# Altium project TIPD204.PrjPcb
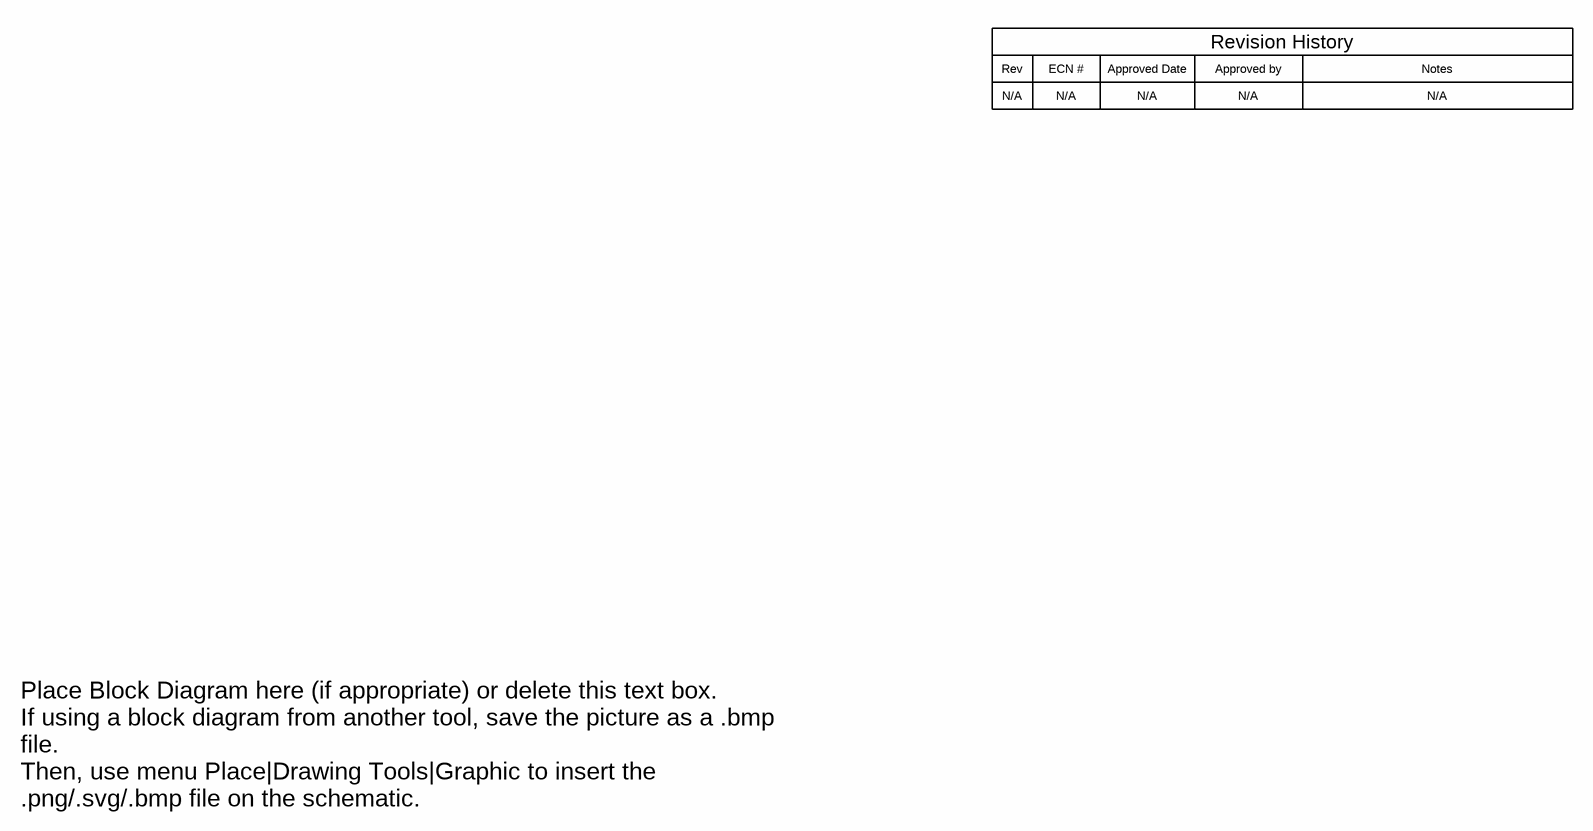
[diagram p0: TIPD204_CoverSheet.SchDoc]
TID: N/A; TechSupport: http://www.ti.com/support; SCH_Rev: A; PRJ_Title: Low-Cost Digitally Programmable Amplifier; PRJ_Number: TIPD204; PRJ_Engineer: CW + JB; PRJ_Customer: Public Release; PCB_Rev: E1; PCB_Layout: JB; CopyrightYear: 2015
3 sheets, 74 parts. Net scope: global (net labels, ports and power ports of the same name join across sheets).
Board file: TIPD204.PcbDoc
Sheets:
  TIPD204_CoverSheet.SchDoc
  TIPD204.SchDoc
  TIPD204_Applications_Hardware.SchDoc

## Sheet TIPD204_CoverSheet.SchDoc
size 431 x 279 mm; Date: Not shown in title block; ApprovedBy: Not shown in title block; CheckedBy: Not shown in title block; Author: Not shown in title block; CompanyName: Not shown in title block; Engineer: Not shown in title block; Organization: Not shown in title block; Address1: Not shown in title block; Address2: Not shown in title block; Address3: Not shown in title block; Address4: Not shown in title block; DocumentNumber: 1; Revision: Use project parameter SCH_Rev; SheetNumber: 1; SheetTotal: 3; PageSetup: Record=PageOptions¦CenterHorizontal=True¦CenterVertical=True¦PrintScale=1.00¦XCorrection=1.00¦YCorrection=1.00¦PrintKind=0¦BorderSize=5000000¦LeftOffset=0¦BottomOffset=0¦Orientation=2¦PaperLength=1000¦PaperWidth=1000¦Scale=100¦PaperSource=15¦PrintQuality=600¦MediaType=1¦DitherType=10¦PaperKind=Letter¦PrintScaleMode=1

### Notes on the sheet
- Rev
- N/A
- ECN #
- Approved Date
- Approved by
- Revision History
- Notes
- Place Block Diagram here (if appropriate) or delete this text box.
  If using a block diagram from another tool, save the picture as a .bmp file.
  Then, use menu Place|Drawing Tools|Graphic to insert the .png/.svg/.bmp file on the schematic.

## Sheet TIPD204.SchDoc: TIPD204
size 431 x 279 mm; Date: Not shown in title block; ApprovedBy: Not shown in title block; CheckedBy: Not shown in title block; Author: Not shown in title block; CompanyName: Not shown in title block; Engineer: CW + JB; Organization: Not shown in title block; Address1: Not shown in title block; Address2: Not shown in title block; Address3: Not shown in title block; Address4: Not shown in title block; DocumentNumber: 1; Revision: Use project parameter SCH_Rev; SheetNumber: 2; SheetTotal: 3; PageSetup: Record=PageOptions¦CenterHorizontal=True¦CenterVertical=True¦PrintScale=1.00¦XCorrection=1.00¦YCorrection=1.00¦PrintKind=0¦BorderSize=5000000¦LeftOffset=0¦BottomOffset=0¦Orientation=2¦PaperLength=1000¦PaperWidth=1000¦Scale=100¦PaperSource=15¦PrintQuality=600¦MediaType=1¦DitherType=10¦PaperKind=Letter¦PrintScaleMode=1
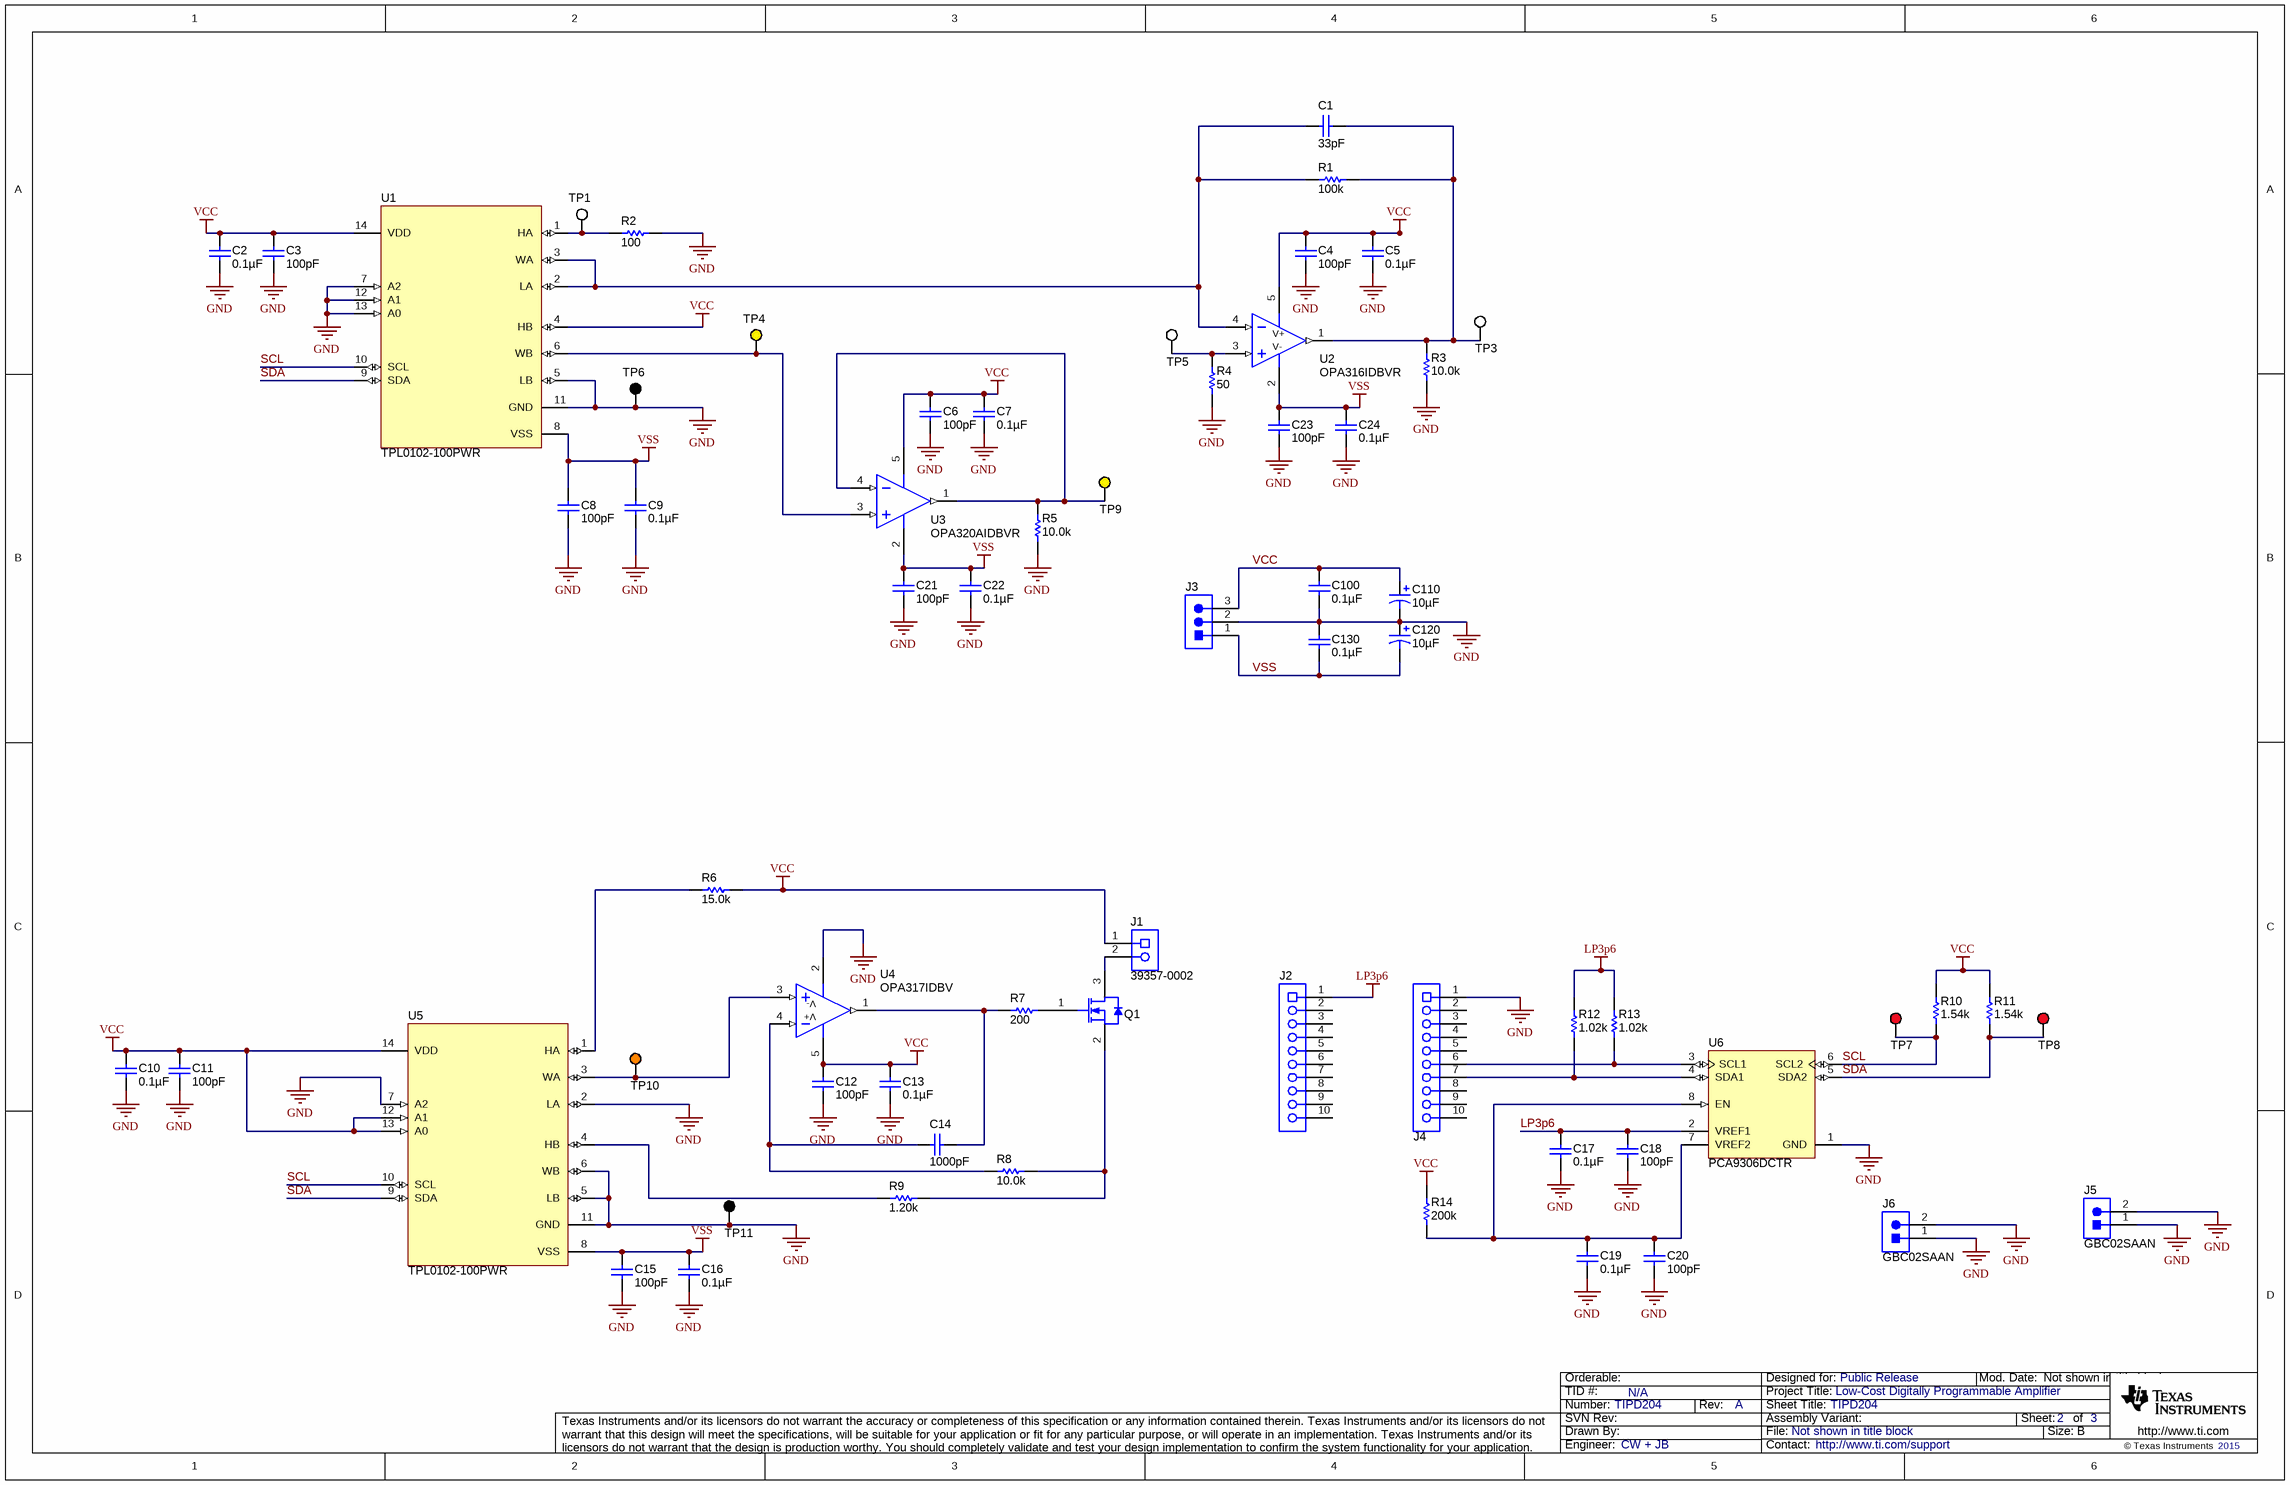
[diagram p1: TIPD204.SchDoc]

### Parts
C1  ValueDisplayed: 33pF  [0603]  (hidden comment: GRM1885C1H330JA01D)
C2  ValueDisplayed: 0.1µF  [0603]  (hidden comment: C0603C104J3RAC)
C3  ValueDisplayed: 100pF  [0603]  (hidden comment: 06033C101KAT2A)
C4  ValueDisplayed: 100pF  [0603]  (hidden comment: 06033C101KAT2A)
C5  ValueDisplayed: 0.1µF  [0603]  (hidden comment: C0603C104J3RAC)
C6  ValueDisplayed: 100pF  [0603]  (hidden comment: 06033C101KAT2A)
C7  ValueDisplayed: 0.1µF  [0603]  (hidden comment: C0603C104J3RAC)
C8  ValueDisplayed: 100pF  [0603]  (hidden comment: 06033C101KAT2A)
C9  ValueDisplayed: 0.1µF  [0603]  (hidden comment: GRM188R71E104KA01D)
C10  ValueDisplayed: 0.1µF  [0603]  (hidden comment: C0603C104J3RAC)
C11  ValueDisplayed: 100pF  [0603]  (hidden comment: 06033C101KAT2A)
C12  ValueDisplayed: 100pF  [0603]  (hidden comment: 06033C101KAT2A)
C13  ValueDisplayed: 0.1µF  [0603]  (hidden comment: C0603C104J3RAC)
C14  ValueDisplayed: 1000pF  [0603]  (hidden comment: 06035A102KAT2A)
C15  ValueDisplayed: 100pF  [0603]  (hidden comment: 06033C101KAT2A)
C16  ValueDisplayed: 0.1µF  [0603]  (hidden comment: C0603C104J3RAC)
C17  ValueDisplayed: 0.1µF  [0603]  (hidden comment: C0603C104J3RAC)
C18  ValueDisplayed: 100pF  [0603]  (hidden comment: 06033C101KAT2A)
C19  ValueDisplayed: 0.1µF  [0603]  (hidden comment: C0603C104J3RAC)
C20  ValueDisplayed: 100pF  [0603]  (hidden comment: 06033C101KAT2A)
C21  ValueDisplayed: 100pF  [0603]  (hidden comment: 06033C101KAT2A)
C22  ValueDisplayed: 0.1µF  [0603]  (hidden comment: C0603C104J3RAC)
C23  ValueDisplayed: 100pF  [0603]  (hidden comment: 06033C101KAT2A)
C24  ValueDisplayed: 0.1µF  [0603]  (hidden comment: C0603C104J3RAC)
C100  ValueDisplayed: 0.1µF  [0603]  (hidden comment: C0603C104J3RAC)
C110  ValueDisplayed: 10µF  [3216-18]  (hidden comment: 293D106X96R3A2TE3)
C120  ValueDisplayed: 10µF  [3216-18]  (hidden comment: 293D106X96R3A2TE3)
C130  ValueDisplayed: 0.1µF  [0603]  (hidden comment: C0603C104J3RAC)
J1  39357-0002  [Molex_39357-0002]
J2  PPTC101LFBN-RC  [CONN_PPTC101LFBN-RC]  (value not drawn)
J3  GBC03SAAN  [Sullins_Gxx03SAAN]  (value not drawn)
J4  PPTC101LFBN-RC  [CONN_PPTC101LFBN-RC]  (value not drawn)
J5  GBC02SAAN  [Sullins_Gxx02SAAN]
J6  GBC02SAAN  [Sullins_Gxx02SAAN]
Q1  SI2304DDS-T1-GE3  [SOT-23]  (value not drawn)
R1  ValueDisplayed: 100k  [0603]  (hidden comment: RC0603FR-07100KL)
R2  ValueDisplayed: 100  [0603]  (hidden comment: RC0603FR-07100RL)
R3  ValueDisplayed: 10.0k  [0603]  (hidden comment: CRCW060310K0FKEA)
R4  ValueDisplayed: 50  [0603]  (hidden comment: CRCW060350R0FKEA)
R5  ValueDisplayed: 10.0k  [0603]  (hidden comment: CRCW060310K0FKEA)
R6  ValueDisplayed: 15.0k  [0603]  (hidden comment: RG1608P-153-B-T5)
R7  ValueDisplayed: 200  [0603]  (hidden comment: RG1608P-201-B-T5)
R8  ValueDisplayed: 10.0k  [0603]  (hidden comment: RG1608P-103-B-T5)
R9  ValueDisplayed: 1.20k  [0603]  (hidden comment: RG1608P-122-B-T5)
R10  ValueDisplayed: 1.54k  [0603]  (hidden comment: CRCW06031K54FKEA)
R11  ValueDisplayed: 1.54k  [0603]  (hidden comment: CRCW06031K54FKEA)
R12  ValueDisplayed: 1.02k  [0603]  (hidden comment: CRCW06031K02FKEA)
R13  ValueDisplayed: 1.02k  [0603]  (hidden comment: CRCW06031K02FKEA)
R14  ValueDisplayed: 200k  [0603]  (hidden comment: CRCW0603200KFKEA)
TP1  5007  [Keystone5007]  (value not drawn)
TP3  5007  [Keystone5007]  (value not drawn)
TP4  5009  [Keystone5009]  (value not drawn)
TP5  5007  [Keystone5007]  (value not drawn)
TP6  5006  [Keystone5006]  (value not drawn)
TP7  5005  [Keystone5005]  (value not drawn)
TP8  5005  [Keystone5005]  (value not drawn)
TP9  5009  [Keystone5009]  (value not drawn)
TP10  5008  [Keystone5008]  (value not drawn)
TP11  5006  [Keystone5006]  (value not drawn)
U1  TPL0102-100PWR  [PW0014A_N]
U2  OPA316IDBVR  [DBV0005A_N]
U3  OPA320AIDBVR  [DBV0005A_N]
U4  OPA317IDBV  [DBV0005A_N]
U5  TPL0102-100PWR  [PW0014A_N]
U6  PCA9306DCTR  [DCT0008A_N]

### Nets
GND: C2.2 C3.2 C4.2 C5.2 C6.2 C7.2 C8.2 C9.2 C10.2 C11.2 C12.2 C13.2 C15.2 C16.2 C17.2 C18.2 C19.2 C20.2 C21.2 C22.2 C23.2 C24.2 C100.2 C110.2(-) C120.1(+) C130.1 J3.2 J4.1 J5.1 J5.2 J6.1 J6.2 R2.2 R3.1 R4.1 R5.1 TP6.1 TP11.1 U1.5(LB) U1.7(A2) U1.11(GND) U1.12(A1) U1.13(A0) U4.2(V-) U5.2(LA) U5.5(LB) U5.6(WB) U5.7(A2) U5.11(GND) U6.1(GND)
LP3p6: C17.1 C18.1 J2.1 R12.2 R13.2 U6.2(VREF1)
VCC: C2.1 C3.1 C4.1 C5.1 C6.1 C7.1 C10.1 C11.1 C12.1 C13.1 C100.1 C110.1(+) J1.1 J3.3 R6.1 R10.2 R11.2 R14.2 U1.4(HB) U1.14(VDD) U2.5(V+) U3.5(V+) U4.5(V+) U5.12(A1) U5.13(A0) U5.14(VDD)
VSS: C8.1 C9.1 C15.1 C16.1 C21.1 C22.1 C23.1 C24.1 C120.2(-) C130.2 J3.1 U1.8(VSS) U2.2(V-) U3.2(V-) U5.8(VSS)
SCL: R10.1 TP7.1 U1.10(SCL) U5.10(SCL) U6.6(SCL2)
SDA: R11.1 TP8.1 U1.9(SDA) U5.9(SDA) U6.5(SDA2)
NetC1_1: C1.1 R1.2 R3.2 TP3.1 U2.1(OUT)
NetC1_2: C1.2 R1.1 U1.2(LA) U1.3(WA) U2.4(IN-)
NetC14_1: C14.1 R7.1 U4.1(OUT)
NetC14_2: C14.2 R8.1 U4.4(IN-)
NetC19_1: C19.1 C20.1 R14.1 U6.7(VREF2) U6.8(EN)
NetJ1_2: J1.2 Q1.3(D)
NetJ4_6: J4.6 R13.1 U6.3(SCL1)
NetJ4_7: J4.7 R12.1 U6.4(SDA1)
NetQ1_1: Q1.1(G) R7.2
NetQ1_2: Q1.2(S) R8.2 R9.1
NetR2_1: R2.1 TP1.1 U1.1(HA)
NetR4_2: R4.2 TP5.1 U2.3(IN+)
NetR5_2: R5.2 TP9.1 U3.1(OUT) U3.4(IN-)
NetR6_2: R6.2 U5.1(HA)
NetR9_2: R9.2 U5.4(HB)
NetTP4_1: TP4.1 U1.6(WB) U3.3(IN+)
NetTP10_1: TP10.1 U4.3(IN+) U5.3(WA)

Not connected (* = marked no-connect by the designer): J2 2 3 4 5 6 7 8 9 10; J4 2 3 4 5 8 9 10

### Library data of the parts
C1 = GRM1885C1H330JA01D: CAP, CERM, 33 pF, 50 V, +/- 5%, C0G/NP0, 0603; Manufacturer: MuRata; Polarized: N; CompType: Capacitor; Value: 33pF; U/M: EA; Cap_F: 0.000000000033; Tolerance_%: 5; Value1: Unknown; VDC_V: 50; Value2: 50V; TaMin_C: -55; TaMax_C: 125; AEC Category: Q200
C2 C5 C7 C10 C13 C16 C17 C19 C22 C24 C100 C130 = C0603C104J3RAC: CAP, CERM, 0.1 µF, 25 V, +/- 5%, X7R, 0603; Manufacturer: Kemet; Polarized: N; CompType: Capacitor; Value: 0.1uF; U/M: EA; Cap_F: 0.0000001; Tolerance_%: 5; Value1: Unknown; VDC_V: 25; Value2: 25V; TaMin_C: -55; TaMax_C: 125
C3 C4 C6 C8 C11 C12 C15 C18 C20 C21 C23 = 06033C101KAT2A: CAP, CERM, 100 pF, 25 V, +/- 10%, X7R, 0603; Manufacturer: AVX; Polarized: N; CompType: Capacitor; Value: 100pF; U/M: EA; Cap_F: 0.0000000001; Tolerance_%: 10; Value1: Unknown; VDC_V: 25; Value2: 25V; TaMin_C: -55; TaMax_C: 125
C9 = GRM188R71E104KA01D: CAP, CERM, 0.1 µF, 25 V, +/- 10%, X7R, 0603; Manufacturer: MuRata; Polarized: N; CompType: Capacitor; Value: 0.1uF; U/M: EA; Cap_F: 0.0000001; Tolerance_%: 10; Value1: Unknown; VDC_V: 25; Value2: 25V; TaMin_C: -55; TaMax_C: 125
C14 = 06035A102KAT2A: CAP, CERM, 1000 pF, 50 V, +/- 10%, C0G/NP0, 0603; Manufacturer: AVX; Polarized: N; CompType: Capacitor; Value: 1000pF; U/M: EA; Cap_F: 0.000000001; Tolerance_%: 10; ESR_ohm: 0.048; Value1: 0.048 ohm; VDC_V: 50; Value2: 50V; TaMin_C: -55; TaMax_C: 125
C110 C120 = 293D106X96R3A2TE3: CAP, TA, 10 µF, 6.3 V, +/- 10%, 3.4 ohm, SMD; Manufacturer: Vishay-Sprague; Polarized: Y; CompType: Capacitor; Value: 10uF; U/M: EA; Cap_F: 0.00001; Tolerance_%: 10; Value1: 3.4 ohm; VDC_V: 6.3; Value2: 6.3V; ESR_ohm: 3.4; IRMS_A: 0.15; TaMin_C: -55; TaMax_C: 125; Cap_Case: A
J1 = 39357-0002: Terminal Block, 3.5 mm, 2x1, Tin, TH; Manufacturer: Molex; SymbolCreator: a0412235; U/M: EA
J2 J4 = PPTC101LFBN-RC: Receptacle, 100mil, 10x1, Tin, TH; Manufacturer: Sullins Connector Solutions; SymbolCreator: a0411947; U/M: EA
J3 = GBC03SAAN: Header, 2.54 mm, 3x1, Gold, TH; Manufacturer: Sullins Connector Solutions; SymbolCreator: a0799628; U/M: EA
J5 J6 = GBC02SAAN: Header, 2.54 mm, 2x1, Gold, TH; Manufacturer: Sullins Connector Solutions; SymbolCreator: a0412235; U/M: EA
Q1 = SI2304DDS-T1-GE3: MOSFET, N-CH, 30 V, 3.3 A, SOT-23; Manufacturer: Vishay-Siliconix; Alternate Manufacturer: None; U/M: EA; ChType: N; Value: 30V; VdsMax_V: 30; Value1: 0.075 ohm; Rdson45_ohm: 0.075; Value2: 4.5 nC; QgTyp_nC: 4.5; Vgs_V: 20; IdsMax_A: 3.3
R1 = RC0603FR-07100KL: RES, 100 k, 1%, 0.1 W, 0603; Manufacturer: Yageo America; CompType: Resistor; Value: 100k; Res_ohm: 100000; Tolerance_%: 1; Power_W: 0.1; Value2: 0.1W; VDC_V: 150; TempCo: 200 ppm/C; EIA_Code: E96; U/M: EA
R2 = RC0603FR-07100RL: RES, 100, 1%, 0.1 W, 0603; Manufacturer: Yageo America; CompType: Resistor; Value: 100; Value_Code: 100R; Tolerance_%: 1; Power_W: 0.1; Value2: 0.1W; VDC_V: 150; TempCo: 200 ppm/C; EIA_Code: E96; U/M: EA
R3 R5 = CRCW060310K0FKEA: RES, 10.0 k, 1%, 0.1 W, 0603; Manufacturer: Vishay-Dale; CompType: Resistor; Value: 10.0k; Res_ohm: 10000; Value_Code: 10k0; Tolerance_%: 1; Power_W: 0.1; Value2: 0.1W; VDC_V: 75; TempCo: 100 ppm/C; EIA_Code: E96; U/M: EA
R4 = CRCW060350R0FKEA: RES, 50, 1%, 0.1 W, 0603; Manufacturer: Vishay-Dale; CompType: Resistor; Value: 50; Value_Code: 50R0; Tolerance_%: 1; Power_W: 0.1; Value2: 0.1W; VDC_V: 75; TempCo: 100 ppm/C; U/M: EA
R6 = RG1608P-153-B-T5: RES, 15.0 k, 0.1%, 0.1 W, 0603; Manufacturer: Susumu Co Ltd; CompType: Resistor; Value: 15.0k; Res_ohm: 15000; Value_Code: 15k0; Tolerance_%: 0.1; Value2: 0.1W; VDC_V: 75; TempCo: 25 ppm/C; EIA_Code: E192; U/M: EA
R7 = RG1608P-201-B-T5: RES, 200, 0.1%, 0.1 W, 0603; Manufacturer: Susumu Co Ltd; CompType: Resistor; Value: 200; Value_Code: 200R; Tolerance_%: 0.1; Value2: 0.1W; VDC_V: 75; TempCo: 25 ppm/C; EIA_Code: E192; U/M: EA
R8 = RG1608P-103-B-T5: RES, 10.0 k, 0.1%, 0.1 W, 0603; Manufacturer: Susumu Co Ltd; CompType: Resistor; Value: 10.0k; Res_ohm: 10000; Value_Code: 10k0; Tolerance_%: 0.1; Value2: 0.1W; VDC_V: 75; TempCo: 25 ppm/C; EIA_Code: E192; U/M: EA
R9 = RG1608P-122-B-T5: RES, 1.20 k, 0.1%, 0.1 W, 0603; Manufacturer: Susumu Co Ltd; CompType: Resistor; Value: 1.20k; Res_ohm: 1200; Value_Code: 1k20; Tolerance_%: 0.1; Value2: 0.1W; VDC_V: 75; TempCo: 25 ppm/C; EIA_Code: E192; U/M: EA
R10 R11 = CRCW06031K54FKEA: RES, 1.54 k, 1%, 0.1 W, 0603; Manufacturer: Vishay-Dale; CompType: Resistor; Value: 1.54k; Res_ohm: 1540; Value_Code: 1k54; Tolerance_%: 1; Power_W: 0.1; Value2: 0.1W; VDC_V: 75; TempCo: 100 ppm/C; EIA_Code: E96; U/M: EA
R12 R13 = CRCW06031K02FKEA: RES, 1.02 k, 1%, 0.1 W, 0603; Manufacturer: Vishay-Dale; CompType: Resistor; Value: 1.02k; Res_ohm: 1020; Value_Code: 1k02; Tolerance_%: 1; Power_W: 0.1; Value2: 0.1W; VDC_V: 75; TempCo: 100 ppm/C; EIA_Code: E96; U/M: EA
R14 = CRCW0603200KFKEA: RES, 200 k, 1%, 0.1 W, 0603; Manufacturer: Vishay-Dale; CompType: Resistor; Value: 200k; Res_ohm: 200000; Tolerance_%: 1; Power_W: 0.1; Value2: 0.1W; VDC_V: 75; TempCo: 100 ppm/C; EIA_Code: E96; U/M: EA
TP1 TP3 TP5 = 5007: Test Point, Compact, White, TH; Manufacturer: Keystone; CompType: Test Point Loop; U/M: EA
TP4 TP9 = 5009: Test Point, Compact, Yellow, TH; Manufacturer: Keystone; CompType: Test Point Loop; U/M: EA
TP6 TP11 = 5006: Test Point, Compact, Black, TH; Manufacturer: Keystone; CompType: Test Point Loop; U/M: EA
TP7 TP8 = 5005: Test Point, Compact, Red, TH; Manufacturer: Keystone; CompType: Test Point Loop; U/M: EA
TP10 = 5008: Test Point, Compact, Orange, TH; Manufacturer: Keystone; CompType: Test Point Loop; U/M: EA
U1 U5 = TPL0102-100PWR: 256-TAPS DUAL CHANNEL DIGITAL POTENTIOMETER WITH NON-VOLATILE MEMORY, PW0014A; Manufacturer: Texas Instruments; SymbolCreator: a0411947; CompType: IC; U/M: EA
U2 = OPA316IDBVR: 10-MHz, Low-Power, Low-Noise, RRIO, 1.8-V CMOS Operational Amplifier, DBV0005A; Alternate PartNumber: OPA316IDBVT; Manufacturer: Texas Instruments; CompType: IC; U/M: EA
U3 = OPA320AIDBVR: Precision, 20 MHz, 0.9 pA Ib, RRIO, CMOS Operational Amplifier, 1.8 to 5.5 V, -40 to 125 degC, 5-pin SOT23 (DBV0005A), Green (RoHS & no Sb/Br); Manufacturer: Texas Instruments; Alternate Manufacturer: None; Alternate PartNumber: Equivalent; CMRR(Min)(dB): 100; IIB(Max)(pA): 0.9; Iq per channel(Max)(mA): 1.75; Number of Channels: 2; Offset Drift(Typ)(uV/C): 1.5; Slew Rate(Typ)(V/us): 10; Sub Family: High Output Current Amplifier (>=50mA), Low Input Bias Current Amp (<=10pA), Low Noise Amp (<=10nV/rtHz), Low Offset Voltage Amplifier (<=500uV), Low Supply Voltage Amplifier (<=2.7V), Precision Amplifier; Total Supply Voltage(Max)(+5V is 5, +/-5V is 10): 5.5; Total Supply Voltage(Min)(+5V is 5, +/-5V is 10): 1.8; Vio (25C)(Max)(mV): 0.15; Vn at 1kHz(Typ)(nV/rtHz): 8.5
U4 = OPA317IDBV: Low-Offset, Rail-to-Rail I/O Operational Amplifier, DBV0005A; Manufacturer: Texas Instruments; CompType: IC; U/M: EA
U6 = PCA9306DCTR: Dual Bi-Directional I2C-Bus and SMBus Voltage Level-Translator, 0 to 5.5 V, -40 to 85 degC, 8-pin SM8 (DCT), Green (RoHS & no Sb/Br); Manufacturer: Texas Instruments; Alternate Manufacturer: None; Alternate PartNumber: Equivalent; SubFamily: I2C Special Function; No. of Outputs: 2; tpd max(ns): 1.5; fSCLK(Max)(MHz): 400; Function: Voltage Translator; Vcc range(V): 0 to 5.5; Enable Pin: Yes; Rating: Catalog

## Sheet TIPD204_Applications_Hardware.SchDoc
size 431 x 279 mm; Date: Not shown in title block; ApprovedBy: Not shown in title block; CheckedBy: Not shown in title block; Author: Not shown in title block; CompanyName: Not shown in title block; DrawnBy: Jared Becker; Engineer: Not shown in title block; Organization: Not shown in title block; Address1: Not shown in title block; Address2: Not shown in title block; Address3: Not shown in title block; Address4: Not shown in title block; DocumentNumber: 1; Revision: Use project parameter SCH_Rev; SheetNumber: 3; SheetTotal: 3; PageSetup: Record=PageOptions¦CenterHorizontal=True¦CenterVertical=True¦PrintScale=1.00¦XCorrection=1.00¦YCorrection=1.00¦PrintKind=0¦BorderSize=5000000¦LeftOffset=0¦BottomOffset=0¦Orientation=2¦PaperLength=1000¦PaperWidth=1000¦Scale=100¦PaperSource=15¦PrintQuality=600¦MediaType=1¦DitherType=10¦PaperKind=Letter¦PrintScaleMode=1
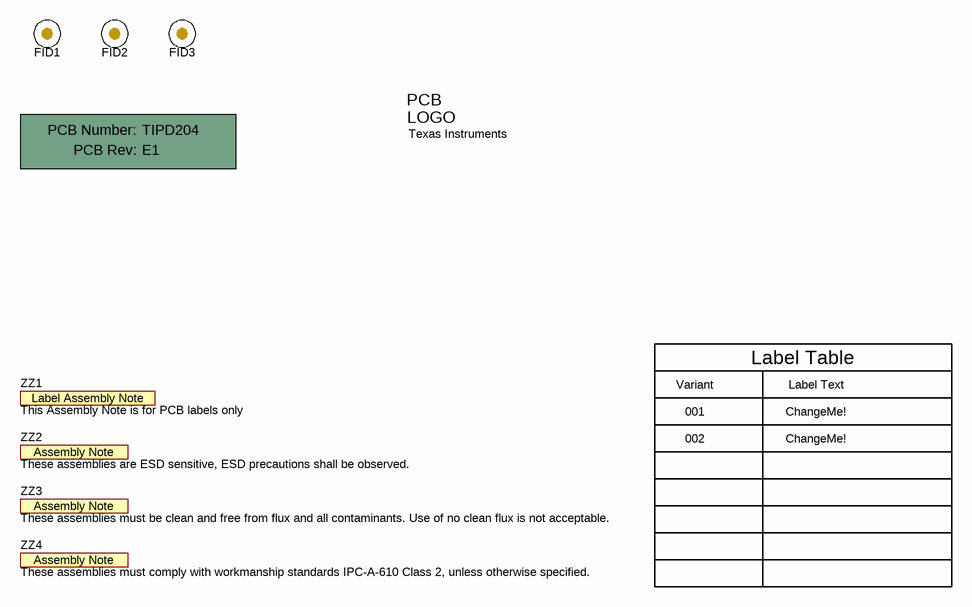
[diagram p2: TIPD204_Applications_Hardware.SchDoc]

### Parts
!PCB1  Printed Circuit Board  (value not drawn)  (mechanical)
FID1  Fiducial  [Fiducial10-20]  (value not drawn)
FID2  Fiducial  [Fiducial10-20]  (value not drawn)
FID3  Fiducial  [Fiducial10-20]  (value not drawn)
Logo1  Texas Instruments  [TI_Symbol_Overlay_Small]  (no BOM)
ZZ1  This Assembly Note is for PCB labels only  [AssemblyNoteLabel]  (no BOM)
ZZ2  These assemblies are ESD sensitive, ESD precautions shall be observed.  [AssemblyNote]  (no BOM)
ZZ3  These assemblies must be clean and free from flux and all contaminants. Use of no clean flux is not acceptable.  [AssemblyNote]  (no BOM)
ZZ4  These assemblies must comply with workmanship standards IPC-A-610 Class 2, unless otherwise specified.  [AssemblyNote]  (no BOM)

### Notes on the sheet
- Variant
- Label Table
- Label Text
- 001
- 002
- ChangeMe!

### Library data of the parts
!PCB1 = PCB: Manufacturer: Any; PartNumber: TIPD204; SymbolCreator: a0412235
FID1-FID3 = Fiducial: Fiducial mark.  There is nothing to buy or mount.; SymbolCreator: codlsc
Logo1 = TI_Logo: Texas Instrument Corporate Signature; SymbolCreator: codlsc
ZZ1 = AssemblyNoteLabel: SymbolCreator: a0412235
ZZ2-ZZ4 = AssemblyNote: SymbolCreator: codlsc

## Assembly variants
001: not fitted FID1 FID2 FID3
